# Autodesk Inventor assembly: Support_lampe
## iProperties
Created: 2011-01
Part Number: Support_lampe
Document SubType Name: Assembly
Designer: eric
Mass: 38.0911 g
Surface Area: 578.522 cm^2
Volume: 38.0911 cm^3
Density: 1 g/cm^3
Norme de conversion: IGES 5.3
Nom du fichier: No Iges File Name specified
Préprocesseur: Autodesk Inventor 2011
Postprocesseur: Build: 342, Release: 2008 SP3 - Date: Tue 05/27/2008
Unités envoyées: MM
Incertitude: 0.01
Author: eric
